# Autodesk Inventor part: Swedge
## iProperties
Shininess: 64.0
Length Units: 11272
Angle Units: 11279
Time Units: 11290
Mass Units: 11283
Length Display Precision: 3
Angle Display Precision: 2
Compacted: True
Part Number: Swedge
Document SubType Name: Modeling
Created: 2005-03
Designer: Admin
Manufacturer: Standard
Standards Organization: Custom
Density: 1 g/cm^3
Density: 0.0
Volumn: 0.0
Area: 0.0
PropertySet Name: Model Information
Control State: 0
Master: False
Checked Out: False
Author: Admin
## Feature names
1. RevolutionFull1
2. Hole1
3. Chamfer1
